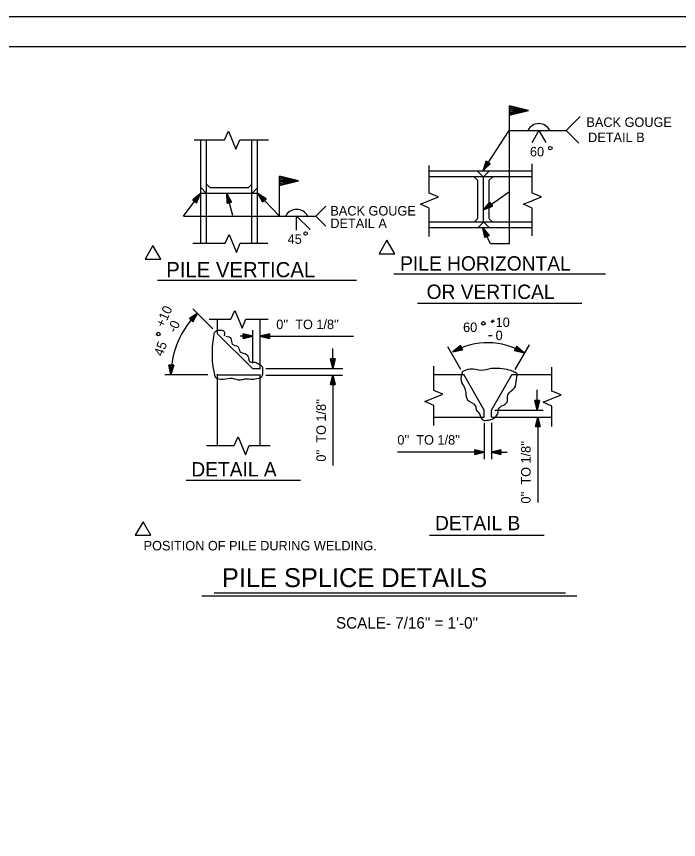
# Model space of a CAD drawing. Extents: x -41 to 191, y -168 to 6.
# Drawn here: x 25.32 to 45.29, y -142.92 to -118.09 of the extents above; entities that cross this region are included whole.
import ezdxf

# ---------------------------------------------------------------- set-up
doc = ezdxf.new("R2010")
doc.units = 0
for name, color, linetype in [('Arrowhead Terminators CELL', 7, 'Continuous'), ('Dimension Lines', 7, 'Continuous'), ('Dimension Lines CELL', 7, 'Continuous'), ('Plan Sheet CELL', 7, 'Continuous'), ('Plot Shape CELL', 7, 'Continuous'), ('Structural Steel Lines CELL', 7, 'Continuous'), ('Text CELL', 7, 'Continuous'), ('User Information Notes CELL', 7, 'Continuous')]:
    doc.layers.add(name, color=color, linetype=linetype)

msp = doc.modelspace()

# ---------------------------------------------------------------- linework, layer by layer
at = {"layer": 'Arrowhead Terminators CELL'}
for points in [[(40.185, -120.93), (40.185, -120.901), (40.757, -120.93), (40.185, -120.872), (40.185, -120.844), (40.757, -120.93), (40.185, -120.815), (40.185, -120.786), (40.757, -120.93), (40.185, -121.073), (40.185, -121.044), (40.757, -120.93), (40.185, -121.015), (40.185, -120.987), (40.757, -120.93), (40.185, -120.958), (40.185, -120.786), (40.185, -121.073), (40.757, -120.93), (40.185, -120.786)], [(39.549, -122.497), (39.561, -122.505), (39.393, -122.737), (39.573, -122.513), (39.585, -122.52), (39.393, -122.737), (39.597, -122.528), (39.609, -122.536), (39.393, -122.737), (39.489, -122.458), (39.501, -122.466), (39.393, -122.737), (39.513, -122.474), (39.525, -122.481), (39.393, -122.737), (39.537, -122.489), (39.609, -122.536), (39.489, -122.458), (39.393, -122.737), (39.609, -122.536)], [(33.253, -123.053), (33.253, -123.024), (33.826, -123.053), (33.253, -122.995), (33.253, -122.967), (33.826, -123.053), (33.253, -122.938), (33.253, -122.91), (33.826, -123.053), (33.253, -123.196), (33.253, -123.167), (33.826, -123.053), (33.253, -123.139), (33.253, -123.11), (33.826, -123.053), (33.253, -123.081), (33.253, -122.91), (33.253, -123.196), (33.826, -123.053), (33.253, -122.91)], [(30.69, -123.671), (30.678, -123.663), (30.861, -123.441), (30.667, -123.654), (30.656, -123.646), (30.861, -123.441), (30.644, -123.637), (30.633, -123.628), (30.861, -123.441), (30.747, -123.714), (30.736, -123.705), (30.861, -123.441), (30.724, -123.697), (30.713, -123.688), (30.861, -123.441), (30.701, -123.68), (30.633, -123.628), (30.747, -123.714), (30.861, -123.441), (30.633, -123.628)], [(31.739, -123.709), (31.725, -123.713), (31.663, -123.433), (31.711, -123.717), (31.697, -123.72), (31.663, -123.433), (31.684, -123.724), (31.67, -123.728), (31.663, -123.433), (31.808, -123.69), (31.794, -123.694), (31.663, -123.433), (31.78, -123.698), (31.766, -123.701), (31.663, -123.433), (31.753, -123.705), (31.67, -123.728), (31.808, -123.69), (31.663, -123.433), (31.67, -123.728)], [(32.794, -123.639), (32.784, -123.649), (32.596, -123.433), (32.773, -123.659), (32.763, -123.669), (32.596, -123.433), (32.753, -123.679), (32.743, -123.689), (32.596, -123.433), (32.846, -123.59), (32.835, -123.599), (32.596, -123.433), (32.825, -123.609), (32.815, -123.619), (32.596, -123.433), (32.804, -123.629), (32.743, -123.689), (32.846, -123.59), (32.596, -123.433), (32.743, -123.689)], [(39.636, -123.757), (39.644, -123.768), (39.402, -123.921), (39.652, -123.78), (39.661, -123.792), (39.402, -123.921), (39.669, -123.803), (39.677, -123.815), (39.402, -123.921), (39.595, -123.698), (39.603, -123.71), (39.402, -123.921), (39.611, -123.722), (39.619, -123.733), (39.402, -123.921), (39.628, -123.745), (39.677, -123.815), (39.595, -123.698), (39.402, -123.921), (39.677, -123.815)], [(39.507, -124.731), (39.494, -124.737), (39.384, -124.472), (39.481, -124.743), (39.468, -124.749), (39.384, -124.472), (39.455, -124.755), (39.442, -124.761), (39.384, -124.472), (39.571, -124.7), (39.559, -124.706), (39.384, -124.472), (39.546, -124.712), (39.533, -124.719), (39.384, -124.472), (39.52, -124.725), (39.442, -124.761), (39.571, -124.7), (39.384, -124.472), (39.442, -124.761)], [(30.585, -127.252), (30.575, -127.242), (30.783, -127.044), (30.565, -127.232), (30.554, -127.222), (30.783, -127.044), (30.544, -127.212), (30.533, -127.202), (30.783, -127.044), (30.637, -127.301), (30.627, -127.291), (30.783, -127.044), (30.616, -127.281), (30.606, -127.271), (30.783, -127.044), (30.596, -127.262), (30.533, -127.202), (30.637, -127.301), (30.783, -127.044), (30.533, -127.202)], [(32.161, -127.732), (32.161, -127.718), (32.447, -127.732), (32.161, -127.704), (32.161, -127.689), (32.447, -127.732), (32.161, -127.675), (32.161, -127.661), (32.447, -127.732), (32.161, -127.804), (32.161, -127.79), (32.447, -127.732), (32.161, -127.775), (32.161, -127.761), (32.447, -127.732), (32.161, -127.747), (32.161, -127.661), (32.161, -127.804), (32.447, -127.732), (32.161, -127.661)], [(32.948, -127.732), (32.948, -127.747), (32.662, -127.732), (32.948, -127.761), (32.948, -127.775), (32.662, -127.732), (32.948, -127.79), (32.948, -127.804), (32.662, -127.732), (32.948, -127.661), (32.948, -127.675), (32.662, -127.732), (32.948, -127.689), (32.948, -127.704), (32.662, -127.732), (32.948, -127.718), (32.948, -127.804), (32.948, -127.661), (32.662, -127.732), (32.948, -127.804)], [(38.741, -128.082), (38.747, -128.095), (38.484, -128.208), (38.754, -128.107), (38.76, -128.12), (38.484, -128.208), (38.766, -128.133), (38.773, -128.146), (38.484, -128.208), (38.709, -128.018), (38.716, -128.03), (38.484, -128.208), (38.722, -128.043), (38.728, -128.056), (38.484, -128.208), (38.735, -128.069), (38.773, -128.146), (38.709, -128.018), (38.484, -128.208), (38.773, -128.146)], [(40.372, -128.103), (40.379, -128.09), (40.626, -128.235), (40.386, -128.077), (40.392, -128.065), (40.626, -128.235), (40.399, -128.052), (40.406, -128.039), (40.626, -128.235), (40.339, -128.166), (40.346, -128.153), (40.626, -128.235), (40.353, -128.141), (40.359, -128.128), (40.626, -128.235), (40.366, -128.115), (40.406, -128.039), (40.339, -128.166), (40.626, -128.235), (40.406, -128.039)], [(34.858, -128.421), (34.873, -128.421), (34.858, -128.708), (34.887, -128.421), (34.901, -128.421), (34.858, -128.708), (34.916, -128.421), (34.93, -128.421), (34.858, -128.708), (34.787, -128.421), (34.801, -128.421), (34.858, -128.708), (34.815, -128.421), (34.83, -128.421), (34.858, -128.708), (34.844, -128.421), (34.93, -128.421), (34.787, -128.421), (34.858, -128.708), (34.93, -128.421)], [(29.99, -128.61), (30.004, -128.611), (29.978, -128.896), (30.019, -128.612), (30.033, -128.612), (29.978, -128.896), (30.047, -128.613), (30.062, -128.614), (29.978, -128.896), (29.919, -128.607), (29.933, -128.608), (29.978, -128.896), (29.947, -128.609), (29.962, -128.609), (29.978, -128.896), (29.976, -128.61), (30.062, -128.614), (29.919, -128.607), (29.978, -128.896), (30.062, -128.614)], [(34.858, -129.192), (34.844, -129.192), (34.858, -128.906), (34.83, -129.192), (34.815, -129.192), (34.858, -128.906), (34.801, -129.192), (34.787, -129.192), (34.858, -128.906), (34.93, -129.192), (34.916, -129.192), (34.858, -128.906), (34.901, -129.192), (34.887, -129.192), (34.858, -128.906), (34.873, -129.192), (34.787, -129.192), (34.93, -129.192), (34.858, -128.906), (34.787, -129.192)], [(41.023, -129.678), (41.037, -129.678), (41.023, -129.964), (41.051, -129.678), (41.066, -129.678), (41.023, -129.964), (41.08, -129.678), (41.094, -129.678), (41.023, -129.964), (40.951, -129.678), (40.966, -129.678), (41.023, -129.964), (40.98, -129.678), (40.994, -129.678), (41.023, -129.964), (41.009, -129.678), (41.094, -129.678), (40.951, -129.678), (41.023, -129.964), (41.094, -129.678)], [(41.04, -130.465), (41.026, -130.465), (41.04, -130.179), (41.011, -130.465), (40.997, -130.465), (41.04, -130.179), (40.983, -130.465), (40.969, -130.465), (41.04, -130.179), (41.112, -130.465), (41.097, -130.465), (41.04, -130.179), (41.083, -130.465), (41.069, -130.465), (41.04, -130.179), (41.054, -130.465), (40.969, -130.465), (41.112, -130.465), (41.04, -130.179), (40.969, -130.465)], [(39.142, -131.235), (39.142, -131.22), (39.428, -131.235), (39.142, -131.206), (39.142, -131.192), (39.428, -131.235), (39.142, -131.177), (39.142, -131.163), (39.428, -131.235), (39.142, -131.306), (39.142, -131.292), (39.428, -131.235), (39.142, -131.278), (39.142, -131.263), (39.428, -131.235), (39.142, -131.249), (39.142, -131.163), (39.142, -131.306), (39.428, -131.235), (39.142, -131.163)], [(39.929, -131.235), (39.929, -131.249), (39.643, -131.235), (39.929, -131.263), (39.929, -131.278), (39.643, -131.235), (39.929, -131.292), (39.929, -131.306), (39.643, -131.235), (39.929, -131.163), (39.929, -131.177), (39.643, -131.235), (39.929, -131.192), (39.929, -131.206), (39.643, -131.235), (39.929, -131.22), (39.929, -131.306), (39.929, -131.163), (39.643, -131.235), (39.929, -131.306)]]:
    msp.add_lwpolyline(points, dxfattribs=at)
at = {"layer": 'Dimension Lines'}
for p, q in [((33.769, -124.544), (33.769, -124.115)), ((33.769, -124.115), (34.173, -124.519))]:
    msp.add_line(p, q, dxfattribs=at)
for centre in [(41.073, -121.694), (33.769, -124.28)]:
    msp.add_arc(centre, 0.369, 26.6279, 153.3721, dxfattribs=at)
at = {"layer": 'Dimension Lines CELL'}
for p, q in [((40.185, -124.938), (40.185, -120.786)), ((40.185, -120.93), (40.757, -120.93)), ((41.894, -121.529), (42.315, -121.107)), ((39.393, -122.737), (40.179, -121.529)), ((40.176, -121.529), (41.894, -121.529)), ((41.073, -121.529), (40.858, -121.9)), ((41.073, -121.529), (41.282, -121.892)), ((41.894, -121.529), (42.282, -121.917)), ((33.252, -124.115), (33.253, -122.91)), ((33.253, -123.053), (33.826, -123.053)), ((39.402, -123.921), (40.187, -123.369)), ((30.36, -124.115), (30.861, -123.441)), ((31.845, -124.097), (31.663, -123.433)), ((32.596, -123.433), (33.252, -124.115)), ((34.343, -124.115), (34.647, -123.811)), ((30.36, -124.115), (33.252, -124.115)), ((33.252, -124.115), (34.343, -124.115)), ((34.343, -124.115), (34.647, -124.418)), ((39.384, -124.472), (39.606, -124.941)), ((39.611, -124.938), (40.185, -124.938)), ((31.242, -127.516), (30.635, -126.909)), ((32.447, -128.553), (32.447, -127.56)), ((32.447, -127.732), (32.062, -127.732)), ((32.662, -127.732), (35.48, -127.732)), ((38.721, -128.742), (38.327, -128.06)), ((40.358, -128.742), (40.787, -127.999)), ((34.858, -128.708), (34.858, -128.112)), ((32.839, -128.708), (35.164, -128.708)), ((31.086, -128.906), (29.792, -128.906)), ((32.839, -128.915), (35.147, -128.915)), ((34.858, -128.906), (34.858, -131.633)), ((41.023, -129.964), (41.023, -129.357)), ((39.745, -129.964), (41.202, -129.964)), ((41.04, -130.179), (41.04, -132.75)), ((39.428, -130.351), (39.428, -131.442)), ((39.643, -130.351), (39.643, -131.442)), ((39.428, -131.235), (36.807, -131.235)), ((39.643, -131.235), (40.119, -131.235))]:
    msp.add_line(p, q, dxfattribs=at)
for centre, radius, start, end in [((32.554, -128.915), 2.576, 133.4378, 179.5922), ((39.532, -130.082), 2.147, 59.3538, 119.2053)]:
    msp.add_arc(centre, radius, start, end, dxfattribs=at)
at = {"layer": 'Plan Sheet CELL'}
msp.add_line((2.412, -118.994), (75.628, -118.994), dxfattribs=at)
at = {"layer": 'Plot Shape CELL'}
msp.add_lwpolyline([(0, -118.093), (75.648, -118.093), (75.648, -168.429), (0, -168.429)], close=True, dxfattribs=at)
at = {"layer": 'Structural Steel Lines CELL'}
for p, q in [((30.682, -121.819), (31.231, -121.819)), ((30.795, -121.819), (31.363, -121.819)), ((30.88, -124.939), (30.88, -121.822)), ((31.051, -123.228), (31.051, -121.822)), ((32.245, -121.819), (32.882, -121.819)), ((32.245, -121.819), (32.917, -121.819)), ((32.422, -124.93), (32.422, -121.822)), ((32.593, -124.93), (32.593, -121.822)), ((37.77, -123.229), (37.77, -122.59)), ((37.77, -123.229), (37.77, -122.592)), ((40.877, -123.229), (40.877, -122.541)), ((40.877, -123.229), (40.877, -122.592)), ((40.863, -122.757), (37.779, -122.757)), ((39.399, -122.927), (39.227, -122.755)), ((39.401, -122.929), (39.572, -122.758)), ((40.863, -122.928), (37.779, -122.928)), ((39.226, -123.031), (39.124, -122.928)), ((39.23, -124.188), (39.23, -123.03)), ((39.401, -124.3), (39.401, -122.927)), ((39.575, -124.188), (39.575, -123.03)), ((39.578, -123.031), (39.681, -122.928)), ((31.049, -123.428), (30.877, -123.257)), ((30.88, -123.254), (30.882, -123.254)), ((31.155, -123.252), (31.051, -123.147)), ((31.051, -124.93), (31.051, -123.232)), ((31.162, -123.254), (32.32, -123.254)), ((32.319, -123.25), (32.422, -123.147)), ((32.424, -123.421), (32.596, -123.25)), ((32.591, -123.254), (32.593, -123.254)), ((30.88, -123.425), (32.593, -123.425)), ((37.77, -124.679), (37.77, -124.111)), ((40.877, -124.679), (40.877, -124.111)), ((37.77, -124.727), (37.77, -124.243)), ((39.205, -124.299), (37.779, -124.299)), ((39.228, -124.194), (39.124, -124.299)), ((40.863, -124.299), (39.208, -124.299)), ((39.401, -124.298), (39.23, -124.469)), ((39.577, -124.459), (39.406, -124.288)), ((39.577, -124.194), (39.681, -124.299)), ((40.877, -124.71), (40.877, -124.243)), ((40.863, -124.47), (37.779, -124.47)), ((30.633, -124.936), (31.248, -124.936)), ((30.812, -124.936), (31.38, -124.936)), ((32.262, -124.936), (32.899, -124.936)), ((32.262, -124.936), (32.851, -124.936)), ((31.133, -127.224), (31.42, -127.224)), ((31.182, -127.224), (31.552, -127.224)), ((31.374, -127.211), (31.374, -127.669)), ((32.434, -127.224), (32.908, -127.224)), ((32.662, -127.224), (32.662, -128.73)), ((32.447, -128.724), (31.376, -127.654)), ((32.662, -128.724), (32.447, -128.724)), ((37.902, -129.182), (37.902, -128.641)), ((37.902, -129.182), (37.902, -128.724)), ((41.468, -129.198), (41.468, -128.674)), ((32.662, -128.913), (31.369, -128.913)), ((31.374, -128.886), (31.374, -130.765)), ((32.662, -128.894), (32.662, -131.022)), ((37.907, -128.891), (38.822, -128.891)), ((39.428, -129.964), (38.808, -128.891)), ((39.643, -129.964), (40.265, -128.887)), ((40.272, -128.891), (41.468, -128.891)), ((37.902, -130.433), (37.902, -130.064)), ((39.428, -130.179), (39.428, -129.964)), ((39.643, -130.179), (39.643, -129.964)), ((39.83, -130.088), (39.832, -130.084)), ((41.468, -130.384), (41.468, -130.08)), ((37.902, -130.416), (37.902, -130.196)), ((37.924, -130.179), (39.428, -130.179)), ((39.643, -130.179), (41.468, -130.179)), ((41.468, -130.466), (41.468, -130.213)), ((31.369, -130.765), (31.369, -131.013)), ((31.051, -131.037), (31.518, -131.037)), ((31.082, -131.037), (31.65, -131.037)), ((32.532, -131.037), (32.974, -131.037))]:
    msp.add_line(p, q, dxfattribs=at)
for points in [[(31.363, -121.819), (31.595, -121.819), (31.715, -121.557), (31.939, -122.094), (32.053, -121.819), (32.245, -121.819)], [(37.77, -124.111), (37.77, -123.88), (37.508, -123.759), (38.045, -123.535), (37.77, -123.422), (37.77, -123.229)], [(40.877, -124.111), (40.877, -123.88), (40.614, -123.759), (41.151, -123.535), (40.877, -123.422), (40.877, -123.229)], [(31.38, -124.936), (31.612, -124.936), (31.732, -124.674), (31.956, -125.211), (32.069, -124.936), (32.262, -124.936)], [(31.552, -127.224), (31.784, -127.224), (31.904, -126.962), (32.128, -127.499), (32.241, -127.224), (32.434, -127.224)], [(37.902, -130.064), (37.902, -129.832), (37.64, -129.712), (38.177, -129.488), (37.902, -129.374), (37.902, -129.182)], [(41.468, -130.08), (41.468, -129.849), (41.206, -129.728), (41.743, -129.504), (41.468, -129.391), (41.468, -129.198)], [(31.65, -131.037), (31.882, -131.037), (32.002, -130.775), (32.227, -131.312), (32.34, -131.037), (32.532, -131.037)]]:
    msp.add_lwpolyline(points, dxfattribs=at)
for points in [[(32.321, -128.414), (32.347, -128.5), (32.485, -128.518), (32.606, -128.561), (32.726, -128.656), (32.735, -128.854), (32.718, -128.958), (32.614, -129.01), (32.433, -129.044), (32.2, -129.036), (32.07, -129.062), (31.837, -129.018), (31.552, -129.044), (31.328, -128.984), (31.294, -128.854), (31.25, -128.656), (31.233, -128.328), (31.233, -128.052), (31.276, -127.732), (31.311, -127.603), (31.44, -127.551)], [(31.423, -127.551), (31.587, -127.594), (31.587, -127.728)], [(31.63, -127.732), (31.785, -127.81), (31.829, -127.974), (31.993, -128.052), (32.07, -128.207), (32.252, -128.285), (32.329, -128.423)], [(38.77, -128.798), (38.727, -129.083), (38.856, -129.351), (38.917, -129.653), (39.158, -129.834), (39.184, -129.969)], [(38.77, -128.798), (39.005, -128.723), (39.342, -128.757), (39.644, -128.706), (39.981, -128.714), (40.222, -128.766), (40.368, -128.831)], [(39.841, -130.085), (39.883, -129.894), (40.117, -129.731), (40.142, -129.506), (40.341, -129.299), (40.401, -129.031), (40.393, -128.841), (40.368, -128.831)], [(39.184, -129.969), (39.279, -130.076), (39.374, -130.257), (39.512, -130.274), (39.599, -130.257), (39.719, -130.214), (39.789, -130.145), (39.823, -130.093)]]:
    msp.add_spline(points, degree=3, dxfattribs=at)
at = {"layer": 'Text CELL'}
for p, q in [((36.702, -125.853), (43.089, -125.853)), ((29.572, -126.049), (35.576, -126.049)), ((37.416, -126.739), (42.375, -126.739)), ((39.628, -127.284), (39.735, -127.284)), ((39.666, -127.335), (39.693, -127.232)), ((39.559, -127.718), (39.666, -127.718)), ((30.439, -132.079), (33.886, -132.079)), ((37.775, -133.736), (41.237, -133.736)), ((31.278, -135.478), (41.88, -135.478)), ((30.905, -135.571), (42.216, -135.571))]:
    msp.add_line(p, q, dxfattribs=at)
for points in [[(36.491, -124.845), (36.254, -125.255), (36.728, -125.255)], [(29.436, -125.006), (29.2, -125.416), (29.673, -125.416)], [(29.136, -133.332), (28.899, -133.742), (29.372, -133.742)]]:
    msp.add_lwpolyline(points, close=True, dxfattribs=at)
for centre in [(41.419, -122.066), (34.04, -124.64), (39.398, -127.351), (29.597, -127.673)]:
    msp.add_circle(centre, 0.0525, dxfattribs=at)

# ---------------------------------------------------------------- texts
for s, height, p in [('BACK GOUGE', 0.2868, (42.508, -121.425)), ('DETAIL B', 0.2868, (42.559, -121.884)), ('60', 0.2868, (40.805, -122.314)), ('BACK GOUGE', 0.2868, (34.785, -124.098)), ('DETAIL A', 0.2868, (34.785, -124.474)), ('45', 0.2868, (33.497, -124.951)), ('PILE HORIZONTAL', 0.43278, (36.89, -125.759)), ('PILE VERTICAL', 0.45797, (29.836, -125.959)), ('OR VERTICAL', 0.43278, (37.688, -126.613)), ("0''  TO 1/8''", 0.28625, (33.155, -127.524)), ('60', 0.2868, (38.789, -127.611)), ('10', 0.2868, (39.77, -127.461)), ('0', 0.287, (39.77, -127.856)), ("0''  TO 1/8''", 0.28625, (36.807, -131.008)), ('DETAIL A', 0.4328, (30.592, -131.968)), ('DETAIL B', 0.4328, (37.942, -133.589)), ('POSITION OF PILE DURING WELDING.', 0.28676, (29.153, -134.199)), ('PILE SPLICE DETAILS', 0.5725, (31.515, -135.307))]:
    msp.add_text(s, height=height, dxfattribs=at).set_placement(p)
for s, height, rotation, p in [('+10', 0.2868, 65.994, (29.764, -127.496)), ('-0', 0.2868, 66.0065, (30.125, -127.657)), ('45', 0.2868, 69.9982, (29.723, -128.361)), ("0''  TO 1/8''", 0.28625, 90, (34.65, -131.521)), ("0''  TO 1/8''", 0.28625, 90, (40.825, -132.786))]:
    msp.add_text(s, height=height, rotation=rotation, dxfattribs=at).set_placement(p)
at = {"layer": 'User Information Notes CELL'}
msp.add_text('SCALE- 7/16" = 1\'-0"', height=0.34348, dxfattribs=at).set_placement((34.955, -136.557))

doc.saveas('drawing.dxf')
